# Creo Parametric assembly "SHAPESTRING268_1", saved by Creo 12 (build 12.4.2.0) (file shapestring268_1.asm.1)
Units: Custom; MM, KILOGRAM, SECS

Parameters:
  PTC_WM_ITERATION = "0"
  PTC_WM_VERSION = "-.0"
  PTC_WM_LIFECYCLE_STATE = "In Work"
  PTC_WM_LIFECYCLE = "MO_CADDocument"
  PTC_WM_CREATED_BY = "Maximilian Roepper (Z0017RMS: MO)"
  PTC_WM_CREATED_ON = "18-Sep-26 11:36:42 AM"
  PTC_WM_MODIFIED_BY = "Maximilian Roepper (Z0017RMS: MO)"
  PTC_WM_MODIFIED_ON = "18-Sep-26 11:36:46 AM"
  PDMLINKNUMBER = "PDM000071455194"
  PTC_WM_NUMBER = "PDM000071455194"

Other parameters: WEIGHT, WEIGHT_FACTOR, WEIGHT_ADD, MC_ERRORS, SUPPLIER

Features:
  1. coordinate system
  2. imported feature
  3. component "SHAPESTRING005_1"
  4. component "SHAPESTRING266_1"
  5. component "SHAPESTRING267_1"

Other named items: DRW_VIEW_ORG, ROUGH-GROB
